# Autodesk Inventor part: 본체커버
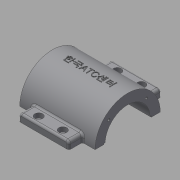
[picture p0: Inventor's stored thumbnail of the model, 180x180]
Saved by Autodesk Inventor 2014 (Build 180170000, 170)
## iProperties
Created: 2015-12
Part Number: 본체커버
Material: 일반
Document SubType Name: Modeling
Designer: mduedu
Density: 1 g/cm^3
Mass: 73.5601 g
Surface Area: 200.806 cm^2
Volume: 73.5601 cm^3
Appearance: 기본값
Author: mduedu
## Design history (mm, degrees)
sketch "스케치1"
  geometry: L1 (45, 40)-(-45, 40); L2 (-45, 40)-(-45, -40); L3 (-45, -40)-(45, -40); L4 (45, -40)-(45, 40); L5 (45, 40)-(-45, -40); L6 (-45, 40)-(45, -40); 1 further point
  constraints: 12 end point, 2 midpoint, 2 parallel, 1 horizontal, 1 perpendicular
  dimensions: "d0" = 90 distance of L2.end L3.end; "d2" = 80 distance of L1.end L2.end
extrude "돌출1" new body sketch "스케치1" distance "d3" = 10; taper "d4" = 0 deg
sketch "스케치2"
  geometry: L1 (0, 40)-(0, -40) reference; C1 r 32.5 at (80, 0); 1 further point
  constraints: 1 centre point
  dimensions: "d5" = 65 diameter of C1; "d6" = 80 distance from line of C1.centre L1
extrude "돌출2" join sketch "스케치2" stored distance "d7" = 75; taper "d8" = 0 deg
sketch "스케치3"
  geometry: L1 (-27.5, -20)-(27.5, -20); L2 (27.5, -20)-(27.5, 20); L3 (27.5, 20)-(-27.5, 20); L4 (-27.5, 20)-(-27.5, -20); L5 (-27.5, -20)-(27.5, 20); L6 (27.5, -20)-(-27.5, 20); 1 further point
  constraints: 12 end point, 2 midpoint, 2 parallel, 1 horizontal, 1 perpendicular
  dimensions: "d9" = 55 distance of L2.end L3.end; "d11" = 40 distance of L1.end L2.end
extrude "돌출3" new body sketch "스케치3" stored distance "d12" = 75; taper "d13" = 0 deg
fillet "모깎기1"
fillet "모깎기2"
feature "결합1"
  node "솔리드2"
fillet "모깎기3" dims "d14" = 10
sketch "스케치4"
  geometry: L1 (-37.5, 47.5)-(37.5, 47.5) reference; L2 (35, 10)-(45, 10) reference; L3 (32.5, 47.5)-(40, 10); L4 (37.5, 47.5)-(37.5, 112.5) reference; L5 (45, 10)-(45, 0) reference; 1 further point
  constraints: 2 end point, 1 midpoint, 1 point on line
  dimensions: "d15" = 5 distance from line of L3.start L4; "d16" = 5 distance from line of L3.end L5
sketch "스케치5"
  geometry: L1 (10, 40)-(10, 30) reference; L2 (10, 35)-(56.569, 22.522); L3 (0, 40)-(10, 40) reference; 2 further points
  constraints: 2 end point, 1 midpoint, 2 other
  dimensions: "d17" = 5 distance from line of L2.start L3; "d18" = 15 deg angle of L2 L3
feature "리브1" dims "d19" = 1, "d20" = 6, "d21" = 0, "d22" = 0, "d23" = 1, "d24" = 1
feature "리브2" dims "d25" = 1, "d26" = 6, "d27" = 0, "d28" = 0, "d29" = 1, "d30" = 1
fillet "모깎기4" dims "d31" = 2
fillet "모깎기5" dims "d32" = 2
fillet "모깎기6" dims "d33" = 2
sketch "스케치6"
  geometry: A1 r 10 centre (-35, 30) between (-35, 40) and (-45, 30) reference; A2 r 10 centre (35, 30) between (45, 30) and (35, 40) reference; A3 r 10 centre (35, -30) between (35, -40) and (45, -30) reference; A4 r 10 centre (-35, -30) between (-45, -30) and (-35, -40) reference; 5 further points
  constraints: 4 coincident
hole "구멍1" sketch "스케치6" at (-35, 30), (35, 30), (35, -30), (-35, -30) diameter "d34" = 7; stored, may be unused: countersink angle "d38" = 90 deg, drill point angle "d40" = 118 deg; dims "d35" = 6, "d36" = 12, "d37" = 3, "d39" = 8
fillet "모깎기7" dims "d41" = 2
hole "구멍2" diameter "d44" = 45; stored, may be unused: countersink angle "d48" = 90 deg, drill point angle "d50" = 118 deg; dims "d42" = 10, "d43" = 10, "d45" = 6, "d46" = 4, "d47" = 2, "d49" = 8
sketch "스케치7" dims "d52" = 26.5
  geometry: L1 (0, 0)-(32.5, 0); L2 (0, 0)-(22.981, 22.981); A1 r 32.5 centre (0, 0) between (32.5, 0) and (22.981, 22.981) reference; 3 further points
  constraints: 4 end point, 2 point on circle, 1 coincident, 1 horizontal, 1 point on line, 3 other
  dimensions: "d51" = 45 deg angle of L2 L1
hole "구멍3" sketch "스케치7" at (18.738, 18.738) diameter "d54" = 2.459; stored, may be unused: countersink angle "d58" = 90 deg, drill point angle "d60" = 118 deg; dims "d55" = 8, "d56" = 4, "d57" = 2, "d59" = 10
sketch "스케치8"
  geometry: L1 (72.5, 31.623)-(72.5, 46); L2 (72.5, 46)-(87.5, 46); L3 (87.5, 46)-(87.5, 31.623); A1 r 32.5 centre (80, 0) between (87.5, 31.623) and (72.5, 31.623) reference; 2 further points
  constraints: 6 end point, 2 point on circle, 1 midpoint, 1 parallel, 1 vertical, 1 vertical alignment
  dimensions: "d64" = 15 distance of L1.end L2.end; "d66" = 46 distance from line of L2 A1.centre
extrude "돌출4" join sketch "스케치8" stored distance "d67" = 50; taper "d68" = 0 deg
fillet "모깎기8" dims "d69" = 3
fillet "모깎기9" dims "d70" = 2
sketch "스케치13"
  geometry: L1 (-46, 80)-(106, 80); L2 (106, 80)-(106, -30); L3 (106, -30)-(-46, -30); L4 (-46, -30)-(-46, 80); L5 (0, 0)-(60, 0) reference; L6 (76, 75.5)-(76, 84.5) reference; C1 r 32.5 at (30, 80) reference; 1 further point
  constraints: 8 end point, 2 parallel, 1 coincident, 1 horizontal, 1 midpoint, 1 perpendicular
  dimensions: "d99" = 30 distance between parallel lines of L3 L5; "d100" = 30 distance between parallel lines of L2 L6
extrude "돌출8" cut sketch "스케치13" stored distance "d97" = 10; taper "d98" = 0 deg
node "작업 평면2"
sketch "스케치14"
  geometry: 2 further points
  constraints: 1 coincident, 1 other
feature "엠보싱1" sketch "스케치14" dims "d28" = 0, "d102" = 0.5, "d103" = 0
feature "립1" dims "d104" = 1, "d105" = 1.1, "d106" = 0, "d107" = 0, "d108" = 3 deg, "d109" = 0
sketch "스케치15"
  geometry: L1 (-3, -1.039)-(-3, -10.834) reference; L2 (47, -10.834)-(47, -1.039) reference; L3 (-3, -5.936)-(47, -5.936); L4 (-15.5, 65.666)-(-15.5, 0.666) reference; L5 (59.5, 0.666)-(59.5, 65.666) reference; L6 (-15.5, 33.166)-(59.5, 33.166); 5 further points
  constraints: 4 end point, 4 midpoint, 2 point on line, 2 symmetric about line
  dimensions: "d110" = 13 distance from line of point (10, -5.936) L1; "d111" = 13 distance from line of point (34, -5.936) L2
sketch "스케치16"
  geometry: 4 further points
hole "구멍5" sketch "스케치16" at (34, -5.936), (10, 72.269), (34, 72.269), (10, -5.936) diameter "d112" = 4.5; stored, may be unused: countersink angle "d116" = 90 deg, drill point angle "d118" = 0 deg; dims "d113" = 6, "d114" = 8, "d115" = 4.6, "d117" = 8
node "솔리드1"
mirror "대칭1"
mirror "대칭2"
pattern_circular "원형 패턴1" dims angle "d62" = 360 deg
mirror "대칭3"
mirror "대칭4"
